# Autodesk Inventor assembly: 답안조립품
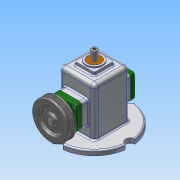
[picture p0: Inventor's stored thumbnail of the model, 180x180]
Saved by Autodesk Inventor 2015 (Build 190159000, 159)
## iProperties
Created: 2018-07
Part Number: 답안조립품
Document SubType Name: Assembly
Designer: user
Author: user
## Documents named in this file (16)
- C:\Users\user\Desktop\480707V1025\답안조립품.iam
- C:\Users\user\Desktop\480707V1025\본체.ipt
- C:\Users\user\Desktop\480707V1025\편심축.ipt
- C:\Users\user\Desktop\480707V1025\V벨트풀리.ipt
- C:\Users\user\Desktop\480707V1025\키 4x4x10.ipt
- C:\Users\user\Desktop\480707V1025\베어링 12x32x10.ipt
- C:\Users\user\Desktop\480707V1025\뒤커버.ipt
- C:\Users\user\Desktop\480707V1025\앞커버.ipt
- C:\Users\user\Desktop\480707V1025\오일 실 12 25 7.ipt
- C:\Users\user\Desktop\480707V1025\볼트 M4.ipt
- C:\Users\user\Desktop\480707V1025\링크.ipt
- C:\Users\user\Desktop\480707V1025\멈춤나사 M3x8.ipt
- C:\Users\user\Desktop\480707V1025\슬라이드.ipt
- C:\Users\user\Desktop\480707V1025\핀 5x18.ipt
- C:\Users\user\Desktop\480707V1025\부시.ipt
- C:\Users\user\Desktop\480707V1025\고정핀 1.2x8.ipt
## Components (3 placed, 3 different names)
1. V벨트풀리:1
2. 핀 5x18:1
3. 고정핀 1.2x8:1
